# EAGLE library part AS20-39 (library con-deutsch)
DEUTSCH Connector
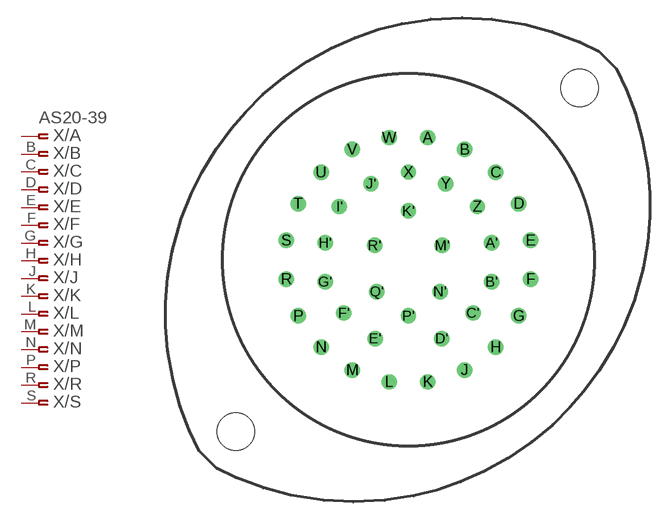
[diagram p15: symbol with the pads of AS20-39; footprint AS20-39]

Designator prefix X; gates /A=PINF_VAL /B=ASPINF /C=ASPINF /D=ASPINF /E=ASPINF /F=ASPINF /G=ASPINF /H=ASPINF /J=ASPINF /K=ASPINF /L=ASPINF /M=ASPINF /N=ASPINF /P=ASPINF /R=ASPINF /S=ASPINF /T=ASPINF /U=ASPINF /V=ASPINF /W=ASPINF /X=ASPINF /Y=ASPINF /Z=ASPINF /A'=PINF_VAL /B'=ASPINF /C'=ASPINF /D'=ASPINF /E'=ASPINF /F'=ASPINF /G'=ASPINF /H'=ASPINF /J'=ASPINF /K'=ASPINF /I'=ASPINF /M'=ASPINF /N'=ASPINF /P'=ASPINF /Q'=ASPINF /R'=ASPINF

## AS20-39 (OC_FARNELL: unknown; OC_NEWARK: unknown)  [AS20-39]
A  /A:1  pas
A'  /A':1  pas
B  /B:1  pas
B'  /B':1  pas
C  /C:1  pas
C'  /C':1  pas
D  /D:1  pas
D'  /D':1  pas
E  /E:1  pas
E'  /E':1  pas
F  /F:1  pas
F'  /F':1  pas
G  /G:1  pas
G'  /G':1  pas
H  /H:1  pas
H'  /H':1  pas
I'  /I':1  pas
J  /J:1  pas
J'  /J':1  pas
K  /K:1  pas
K'  /K':1  pas
L  /L:1  pas
M  /M:1  pas
M'  /M':1  pas
N  /N:1  pas
N'  /N':1  pas
P  /P:1  pas
P'  /P':1  pas
Q'  /Q':1  pas
R  /R:1  pas
R'  /R':1  pas
S  /S:1  pas
T  /T:1  pas
U  /U:1  pas
V  /V:1  pas
W  /W:1  pas
X  /X:1  pas
Y  /Y:1  pas
Z  /Z:1  pas

## Footprint AS20-39 (pad centres in mm)
DEUTSCH Connector
drill 0.813 round: A 1.651,10.439; A' 7.112,1.448; B 4.801,9.423; B' 7.112,-1.88; C 7.468,7.468; C' 5.512,-4.547; D 9.423,4.801; D' 2.845,-6.731; E 10.439,1.651; E' -2.845,-6.731; F 10.439,-1.651; F' -5.512,-4.547; G 9.423,-4.801; G' -7.112,-1.88; H 7.468,-7.468; H' -7.112,1.448; I' -5.893,4.547; J 4.801,-9.423; J' -3.2,6.502; K 1.651,-10.439; K' 0,4.166; L -1.651,-10.439; M -4.801,-9.423; M' 2.896,1.219; N -7.468,-7.468; N' 2.692,-2.718; P -9.423,-4.801; P' 0,-4.801; Q' -2.692,-2.718; R -10.439,-1.651; R' -2.896,1.219; S -10.439,1.651; T -9.423,4.801; U -7.468,7.468; V -4.801,9.423; W -1.651,10.439; X 0,7.493; Y 3.2,6.502; Z 5.893,4.547
hole 3.2 at -14.764,-14.7
hole 3.2 at 14.636,14.7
